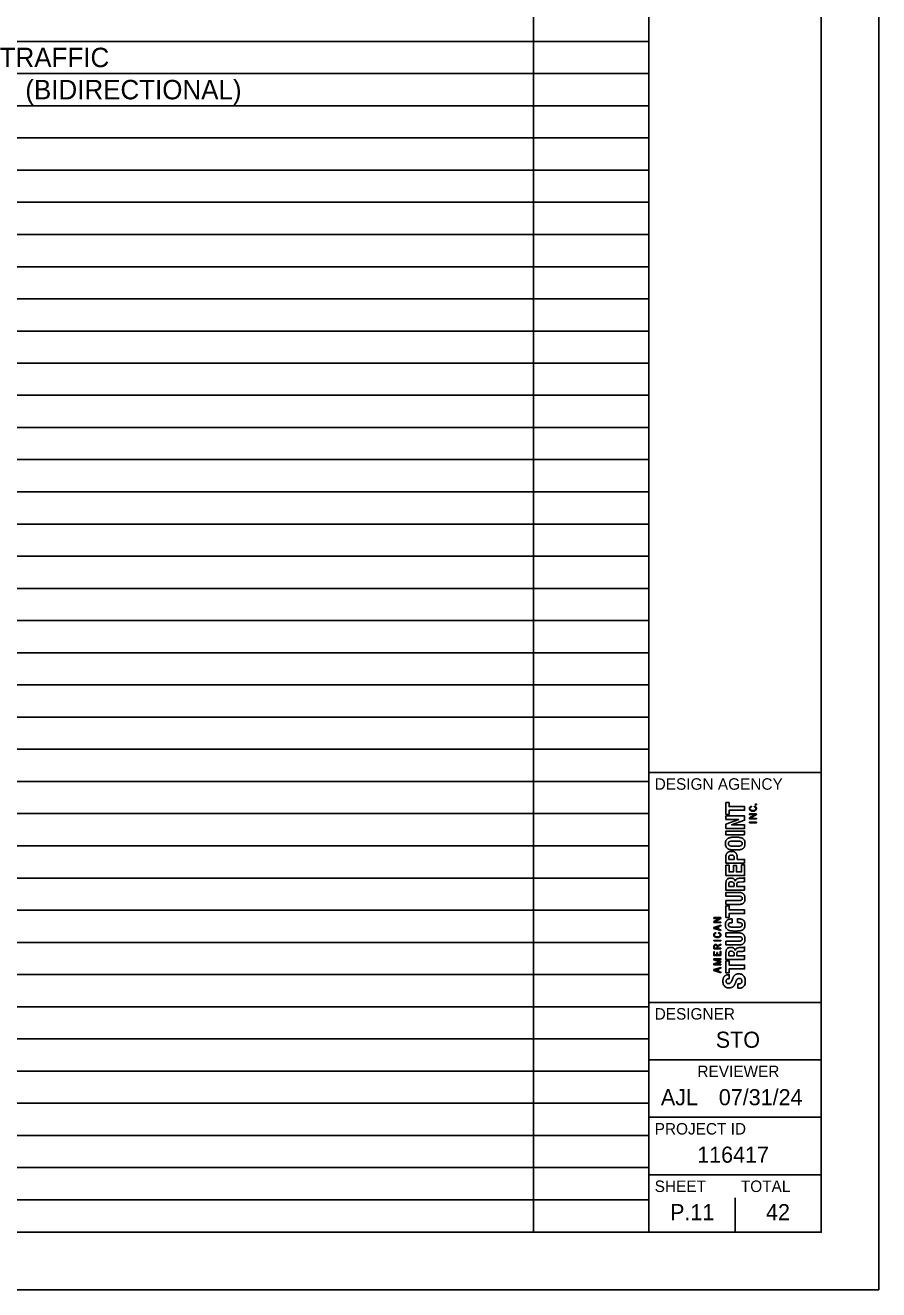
# Model space of a CAD drawing. Extents: x 0 to 34, y 0 to 22.
# Drawn here: x 26.57 to 34, y 0 to 11 of the extents above; entities that cross this region are included whole.
import ezdxf

# ---------------------------------------------------------------- set-up
doc = ezdxf.new("R2010")
doc.units = 0
for name, color, linetype in [('SH_Border', 7, 'Continuous'), ('SH_Cut_Line', 7, 'Continuous'), ('SH_Data', 7, 'Continuous')]:
    doc.layers.add(name, color=color, linetype=linetype)

msp = doc.modelspace()

# ---------------------------------------------------------------- linework, layer by layer
at = {"layer": 'SH_Border'}
for p, q in [((32, 0.5), (32, 21.5)), ((32, 4.5), (33.5, 4.5)), ((32, 2.5), (33.5, 2.5)), ((32, 2), (33.5, 2)), ((32, 1.5), (33.5, 1.5)), ((32, 1), (33.5, 1))]:
    msp.add_line(p, q, dxfattribs=at)
msp.add_lwpolyline([(1.5, 21.5), (33.5, 21.5), (33.5, 0.5), (1.5, 0.5)], close=True, dxfattribs=at)
at = {"layer": 'SH_Cut_Line'}
msp.add_lwpolyline([(0, 0), (34, 0), (34, 22), (0, 22)], close=True, dxfattribs=at)
at = {"layer": 'SH_Data'}
for p, q in [((30.995, 0.502), (30.995, 21.5)), ((32, 0.502), (32, 21.5)), ((1.5, 10.861), (32, 10.861)), ((1.5, 10.581), (32, 10.581)), ((1.5, 10.301), (32, 10.301)), ((1.5, 10.021), (32, 10.021)), ((1.5, 9.741), (32, 9.741)), ((1.5, 9.461), (32, 9.461)), ((1.5, 9.181), (32, 9.181)), ((1.5, 8.901), (32, 8.901)), ((1.5, 8.621), (32, 8.621)), ((1.5, 8.341), (32, 8.341)), ((1.5, 8.062), (32, 8.062)), ((1.5, 7.782), (32, 7.782)), ((1.5, 7.502), (32, 7.502)), ((1.5, 7.222), (32, 7.222)), ((1.5, 6.942), (32, 6.942)), ((1.5, 6.662), (32, 6.662)), ((1.5, 6.382), (32, 6.382)), ((1.5, 6.102), (32, 6.102)), ((1.5, 5.822), (32, 5.822)), ((1.5, 5.542), (32, 5.542)), ((1.5, 5.262), (32, 5.262)), ((1.5, 4.982), (32, 4.982)), ((1.5, 4.702), (32, 4.702)), ((1.5, 4.422), (32, 4.422)), ((1.5, 4.142), (32, 4.142)), ((1.5, 3.862), (32, 3.862)), ((1.5, 3.582), (32, 3.582)), ((32.75, 3.5), (32.75, 3.5)), ((32.75, 3.5), (32.75, 3.5)), ((1.5, 3.302), (32, 3.302)), ((1.5, 3.022), (32, 3.022)), ((1.5, 2.742), (32, 2.742)), ((1.5, 2.462), (32, 2.462)), ((1.5, 2.182), (32, 2.182)), ((1.5, 1.902), (32, 1.902)), ((1.5, 1.622), (32, 1.622)), ((1.5, 1.342), (32, 1.342)), ((1.5, 1.062), (32, 1.062)), ((1.5, 0.782), (32, 0.782)), ((32.75, 0.5), (32.75, 0.8)), ((32.375, 0.675), (32.375, 0.675)), ((1.5, 0.502), (32, 0.502))]:
    msp.add_line(p, q, dxfattribs=at)
for points in [[(32.67, 4.239), (32.697, 4.239), (32.697, 4.204), (32.833, 4.204), (32.833, 4.171), (32.697, 4.171), (32.697, 4.135), (32.67, 4.135), (32.67, 4.239)], [(32.935, 4.218), (32.927, 4.218), (32.927, 4.225), (32.935, 4.225), (32.935, 4.218)], [(32.67, 4.051), (32.781, 4.091), (32.781, 4.092), (32.67, 4.092), (32.67, 4.122), (32.833, 4.122), (32.833, 4.084), (32.719, 4.044), (32.719, 4.044), (32.833, 4.044), (32.833, 4.013), (32.67, 4.013), (32.67, 4.051)], [(32.875, 4.096), (32.875, 4.105), (32.925, 4.134), (32.925, 4.134), (32.875, 4.134), (32.875, 4.139), (32.935, 4.139), (32.935, 4.134), (32.88, 4.102), (32.88, 4.101), (32.935, 4.101), (32.935, 4.096), (32.875, 4.096)], [(32.833, 3.957), (32.67, 3.957), (32.67, 3.99), (32.833, 3.99), (32.833, 3.957)], [(32.875, 4.061), (32.875, 4.067), (32.935, 4.067), (32.935, 4.061), (32.875, 4.061)], [(32.833, 3.712), (32.67, 3.712), (32.67, 3.769)], [(32.694, 3.744), (32.743, 3.744), (32.743, 3.759)], [(32.694, 3.758), (32.694, 3.744)], [(32.768, 3.762), (32.768, 3.744), (32.833, 3.744), (32.833, 3.712)], [(32.67, 3.694), (32.697, 3.694), (32.697, 3.635), (32.735, 3.635), (32.735, 3.69), (32.762, 3.69), (32.762, 3.635), (32.806, 3.635), (32.806, 3.696), (32.833, 3.696), (32.833, 3.603), (32.67, 3.603), (32.67, 3.694)], [(32.833, 3.476), (32.67, 3.476), (32.67, 3.537)], [(32.694, 3.525), (32.694, 3.509)], [(32.694, 3.509), (32.741, 3.509), (32.741, 3.523)], [(32.752, 3.554), (32.752, 3.554)], [(32.764, 3.527), (32.764, 3.509), (32.833, 3.509), (32.833, 3.476)], [(32.816, 3.548), (32.784, 3.547)], [(32.832, 3.587), (32.833, 3.587), (32.833, 3.552)], [(32.67, 3.341), (32.697, 3.341), (32.697, 3.305), (32.833, 3.305), (32.833, 3.273), (32.697, 3.273), (32.697, 3.237), (32.67, 3.237), (32.67, 3.341)], [(32.565, 3.194), (32.565, 3.203), (32.615, 3.231), (32.615, 3.231), (32.565, 3.231), (32.565, 3.237), (32.625, 3.237), (32.625, 3.231), (32.569, 3.199), (32.569, 3.199), (32.625, 3.199), (32.625, 3.194), (32.565, 3.194)], [(32.625, 3.125), (32.565, 3.144), (32.565, 3.152), (32.625, 3.171), (32.625, 3.165), (32.605, 3.159), (32.605, 3.137), (32.625, 3.131), (32.625, 3.125)], [(32.601, 3.138), (32.601, 3.158), (32.569, 3.148), (32.569, 3.148), (32.601, 3.138)], [(32.565, 3.034), (32.565, 3.039), (32.625, 3.039), (32.625, 3.034), (32.565, 3.034)], [(32.596, 2.992), (32.625, 3.006), (32.625, 3), (32.597, 2.987), (32.597, 2.971), (32.625, 2.971), (32.625, 2.966), (32.565, 2.966), (32.565, 2.986)], [(32.569, 2.971), (32.593, 2.971), (32.593, 2.986)], [(32.569, 2.986), (32.569, 2.971)], [(32.832, 2.984), (32.833, 2.984), (32.833, 2.949)], [(32.625, 2.907), (32.565, 2.907), (32.565, 2.941), (32.569, 2.941), (32.569, 2.913), (32.591, 2.913), (32.591, 2.933), (32.596, 2.933), (32.596, 2.913), (32.62, 2.913), (32.62, 2.943), (32.625, 2.943), (32.625, 2.907)], [(32.625, 2.826), (32.565, 2.826), (32.565, 2.836), (32.615, 2.852), (32.615, 2.853), (32.565, 2.869), (32.565, 2.879), (32.625, 2.879), (32.625, 2.873), (32.569, 2.873), (32.569, 2.873), (32.625, 2.855), (32.625, 2.85), (32.569, 2.832), (32.569, 2.832), (32.625, 2.832), (32.625, 2.826)], [(32.833, 2.873), (32.67, 2.873), (32.67, 2.934)], [(32.694, 2.922), (32.694, 2.906)], [(32.694, 2.906), (32.741, 2.906), (32.741, 2.92)], [(32.752, 2.951), (32.752, 2.951)], [(32.764, 2.924), (32.764, 2.906), (32.833, 2.906), (32.833, 2.873)], [(32.816, 2.944), (32.784, 2.944)], [(32.625, 2.758), (32.565, 2.777), (32.565, 2.785), (32.625, 2.804), (32.625, 2.798), (32.605, 2.792), (32.605, 2.769), (32.625, 2.763), (32.625, 2.758)], [(32.601, 2.771), (32.601, 2.791), (32.569, 2.781), (32.569, 2.781), (32.601, 2.771)], [(32.67, 2.86), (32.697, 2.86), (32.697, 2.824), (32.833, 2.824), (32.833, 2.791), (32.697, 2.791), (32.697, 2.756), (32.67, 2.756), (32.67, 2.86)]]:
    msp.add_lwpolyline(points, dxfattribs=at)
for points in [[(32.893, 4.201), (32.889, 4.199), (32.885, 4.197), (32.883, 4.195), (32.88, 4.193), (32.879, 4.19), (32.879, 4.186), (32.879, 4.183), (32.88, 4.181), (32.881, 4.178), (32.882, 4.176), (32.884, 4.175), (32.887, 4.173), (32.889, 4.172), (32.892, 4.171), (32.895, 4.17), (32.898, 4.169), (32.902, 4.169), (32.905, 4.169), (32.909, 4.169), (32.912, 4.169), (32.915, 4.17), (32.919, 4.171), (32.921, 4.172), (32.924, 4.173), (32.926, 4.175), (32.928, 4.176), (32.929, 4.179), (32.931, 4.181), (32.931, 4.184), (32.931, 4.187), (32.931, 4.189), (32.931, 4.191), (32.93, 4.193), (32.929, 4.194), (32.928, 4.196), (32.927, 4.197), (32.926, 4.198), (32.924, 4.199), (32.922, 4.2), (32.921, 4.2), (32.919, 4.201), (32.917, 4.202), (32.917, 4.202), (32.918, 4.207), (32.918, 4.207), (32.92, 4.206), (32.923, 4.205), (32.925, 4.204), (32.927, 4.203), (32.929, 4.202), (32.931, 4.2), (32.932, 4.199), (32.934, 4.197), (32.934, 4.195), (32.935, 4.192), (32.936, 4.19), (32.936, 4.187), (32.936, 4.183), (32.935, 4.18), (32.934, 4.177), (32.932, 4.174), (32.93, 4.172), (32.927, 4.17), (32.925, 4.168), (32.921, 4.166), (32.918, 4.165), (32.914, 4.164), (32.91, 4.164), (32.905, 4.164), (32.901, 4.164), (32.896, 4.164), (32.893, 4.165), (32.889, 4.166), (32.886, 4.168), (32.883, 4.17), (32.88, 4.172), (32.878, 4.174), (32.877, 4.177), (32.875, 4.18), (32.875, 4.183), (32.875, 4.187), (32.875, 4.189), (32.875, 4.192), (32.876, 4.194), (32.877, 4.196), (32.878, 4.198), (32.88, 4.199), (32.881, 4.201), (32.883, 4.202), (32.885, 4.203), (32.887, 4.204), (32.889, 4.205), (32.892, 4.206), (32.892, 4.206), (32.893, 4.201), (32.893, 4.201)], [(32.751, 3.826), (32.739, 3.826), (32.727, 3.826), (32.717, 3.828), (32.706, 3.829), (32.697, 3.831), (32.69, 3.835), (32.682, 3.839), (32.677, 3.845), (32.672, 3.852), (32.668, 3.859), (32.666, 3.869), (32.666, 3.882), (32.666, 3.894), (32.668, 3.904), (32.672, 3.911), (32.677, 3.918), (32.682, 3.924), (32.69, 3.928), (32.697, 3.932), (32.706, 3.934), (32.717, 3.936), (32.727, 3.937), (32.739, 3.937), (32.751, 3.937), (32.758, 3.937), (32.764, 3.937), (32.771, 3.937)], [(32.751, 3.859), (32.762, 3.859), (32.771, 3.859), (32.779, 3.859), (32.787, 3.86), (32.793, 3.861), (32.798, 3.863), (32.803, 3.864), (32.806, 3.867), (32.808, 3.87), (32.81, 3.873), (32.812, 3.877), (32.812, 3.882), (32.812, 3.886), (32.81, 3.89), (32.808, 3.893), (32.806, 3.896), (32.803, 3.899), (32.798, 3.9), (32.793, 3.902), (32.787, 3.903), (32.779, 3.904), (32.771, 3.904), (32.762, 3.904), (32.751, 3.904), (32.74, 3.904), (32.731, 3.904), (32.723, 3.904), (32.716, 3.903), (32.709, 3.902), (32.704, 3.9), (32.7, 3.899), (32.696, 3.896), (32.694, 3.893), (32.692, 3.89), (32.691, 3.886), (32.691, 3.882), (32.691, 3.877), (32.692, 3.873), (32.694, 3.87), (32.696, 3.867), (32.7, 3.864), (32.704, 3.863), (32.709, 3.861), (32.716, 3.86), (32.723, 3.859), (32.731, 3.859), (32.74, 3.859), (32.751, 3.859)], [(32.771, 3.937), (32.776, 3.936), (32.781, 3.936), (32.785, 3.936), (32.796, 3.934), (32.805, 3.932), (32.812, 3.928), (32.82, 3.924), (32.825, 3.918), (32.83, 3.911), (32.834, 3.904), (32.836, 3.894), (32.836, 3.882), (32.836, 3.869), (32.834, 3.859), (32.83, 3.852), (32.825, 3.845), (32.82, 3.839), (32.812, 3.835), (32.805, 3.831), (32.796, 3.829), (32.785, 3.828), (32.775, 3.826), (32.763, 3.826), (32.751, 3.826)], [(32.67, 3.769), (32.67, 3.777), (32.671, 3.784), (32.674, 3.79), (32.677, 3.796), (32.68, 3.8), (32.685, 3.804), (32.689, 3.807), (32.695, 3.81), (32.701, 3.812), (32.706, 3.813), (32.712, 3.814), (32.719, 3.814), (32.727, 3.814), (32.734, 3.813), (32.741, 3.81), (32.747, 3.808), (32.752, 3.804), (32.756, 3.8), (32.76, 3.795), (32.763, 3.79), (32.765, 3.783), (32.767, 3.777), (32.768, 3.77), (32.768, 3.762)], [(32.743, 3.759), (32.743, 3.766), (32.741, 3.771), (32.737, 3.775), (32.733, 3.779), (32.727, 3.781), (32.719, 3.781), (32.711, 3.781), (32.705, 3.779), (32.7, 3.776), (32.696, 3.772), (32.694, 3.766), (32.694, 3.758)], [(32.67, 3.537), (32.67, 3.551), (32.673, 3.562), (32.68, 3.569), (32.687, 3.577), (32.698, 3.581), (32.712, 3.581), (32.723, 3.581), (32.732, 3.579), (32.739, 3.574), (32.745, 3.57), (32.75, 3.563), (32.752, 3.554)], [(32.741, 3.523), (32.741, 3.531), (32.739, 3.537), (32.735, 3.542), (32.732, 3.546), (32.725, 3.548), (32.717, 3.548), (32.702, 3.548), (32.694, 3.54), (32.694, 3.525)], [(32.752, 3.554), (32.753, 3.559), (32.755, 3.564), (32.757, 3.567), (32.759, 3.571), (32.762, 3.573), (32.766, 3.575), (32.769, 3.577), (32.774, 3.578), (32.78, 3.579), (32.786, 3.58), (32.794, 3.58), (32.802, 3.58), (32.811, 3.58), (32.818, 3.581), (32.822, 3.582), (32.827, 3.582), (32.83, 3.584), (32.832, 3.587)], [(32.784, 3.547), (32.778, 3.546), (32.773, 3.545), (32.769, 3.542), (32.766, 3.539), (32.764, 3.534), (32.764, 3.527)], [(32.833, 3.552), (32.831, 3.55), (32.828, 3.549), (32.825, 3.549), (32.822, 3.548), (32.819, 3.548), (32.816, 3.548)], [(32.67, 3.385), (32.67, 3.385), (32.783, 3.385), (32.783, 3.385), (32.787, 3.385), (32.791, 3.385), (32.795, 3.386), (32.798, 3.387), (32.801, 3.388), (32.803, 3.389), (32.806, 3.39), (32.808, 3.392), (32.809, 3.395), (32.811, 3.397), (32.812, 3.401), (32.812, 3.404), (32.812, 3.408), (32.811, 3.411), (32.809, 3.414), (32.808, 3.417), (32.806, 3.418), (32.803, 3.42), (32.801, 3.421), (32.798, 3.422), (32.795, 3.423), (32.791, 3.423), (32.787, 3.424), (32.783, 3.424), (32.783, 3.424), (32.67, 3.424), (32.67, 3.424), (32.67, 3.424), (32.67, 3.457), (32.67, 3.457), (32.67, 3.457), (32.783, 3.457), (32.783, 3.457), (32.794, 3.457), (32.802, 3.455), (32.809, 3.452), (32.816, 3.449), (32.821, 3.445), (32.825, 3.441), (32.829, 3.436), (32.832, 3.43), (32.834, 3.424), (32.835, 3.418), (32.836, 3.411), (32.836, 3.404), (32.836, 3.398), (32.835, 3.391), (32.834, 3.385), (32.833, 3.379), (32.83, 3.373), (32.826, 3.368), (32.822, 3.363), (32.817, 3.36), (32.81, 3.357), (32.803, 3.354), (32.794, 3.352), (32.783, 3.352), (32.783, 3.352), (32.67, 3.352), (32.67, 3.352), (32.67, 3.352), (32.67, 3.385), (32.67, 3.385)], [(32.725, 3.193), (32.713, 3.193), (32.704, 3.192), (32.699, 3.189), (32.693, 3.186), (32.691, 3.181), (32.691, 3.174), (32.691, 3.17), (32.692, 3.166), (32.694, 3.163), (32.696, 3.161), (32.7, 3.159), (32.705, 3.157), (32.71, 3.156), (32.716, 3.155), (32.724, 3.154), (32.732, 3.153), (32.742, 3.153), (32.753, 3.153), (32.766, 3.153), (32.776, 3.153), (32.783, 3.154), (32.791, 3.155), (32.797, 3.156), (32.801, 3.158), (32.805, 3.16), (32.808, 3.162), (32.809, 3.165), (32.811, 3.168), (32.812, 3.171), (32.812, 3.174), (32.812, 3.177), (32.811, 3.18), (32.81, 3.182), (32.809, 3.185), (32.807, 3.187), (32.804, 3.189), (32.801, 3.191), (32.797, 3.192), (32.792, 3.193), (32.786, 3.194), (32.779, 3.195), (32.77, 3.195), (32.77, 3.195), (32.77, 3.228), (32.77, 3.228), (32.779, 3.228), (32.787, 3.227), (32.795, 3.226), (32.803, 3.224), (32.81, 3.222), (32.816, 3.218), (32.822, 3.214), (32.827, 3.209), (32.831, 3.202), (32.834, 3.196), (32.836, 3.187), (32.836, 3.176), (32.836, 3.163), (32.834, 3.154), (32.83, 3.146), (32.825, 3.139), (32.82, 3.133), (32.812, 3.129), (32.805, 3.126), (32.796, 3.123), (32.785, 3.122), (32.775, 3.121), (32.763, 3.12), (32.751, 3.12), (32.739, 3.12), (32.727, 3.121), (32.717, 3.122), (32.706, 3.123), (32.697, 3.126), (32.69, 3.129), (32.682, 3.133), (32.677, 3.139), (32.672, 3.146), (32.668, 3.154), (32.666, 3.163), (32.666, 3.176), (32.666, 3.188), (32.668, 3.197), (32.672, 3.204), (32.676, 3.21), (32.681, 3.215), (32.687, 3.219), (32.692, 3.222), (32.699, 3.224), (32.706, 3.225), (32.712, 3.226), (32.719, 3.226), (32.725, 3.226), (32.725, 3.226), (32.725, 3.193), (32.725, 3.193)], [(32.582, 3.101), (32.578, 3.1), (32.575, 3.098), (32.572, 3.095), (32.57, 3.093), (32.569, 3.09), (32.569, 3.086), (32.569, 3.083), (32.569, 3.081), (32.571, 3.079), (32.572, 3.077), (32.574, 3.075), (32.576, 3.074), (32.579, 3.072), (32.581, 3.071), (32.585, 3.07), (32.588, 3.07), (32.591, 3.069), (32.595, 3.069), (32.598, 3.069), (32.602, 3.07), (32.605, 3.07), (32.608, 3.071), (32.611, 3.072), (32.613, 3.074), (32.616, 3.075), (32.618, 3.077), (32.619, 3.079), (32.62, 3.081), (32.621, 3.084), (32.621, 3.087), (32.621, 3.089), (32.62, 3.091), (32.62, 3.093), (32.619, 3.095), (32.618, 3.096), (32.617, 3.097), (32.615, 3.098), (32.614, 3.099), (32.612, 3.1), (32.61, 3.101), (32.608, 3.102), (32.606, 3.102), (32.606, 3.102), (32.607, 3.107), (32.607, 3.107), (32.61, 3.107), (32.612, 3.106), (32.615, 3.105), (32.617, 3.104), (32.619, 3.102), (32.62, 3.101), (32.622, 3.099), (32.623, 3.097), (32.624, 3.095), (32.625, 3.093), (32.625, 3.09), (32.625, 3.087), (32.625, 3.083), (32.625, 3.08), (32.623, 3.077), (32.622, 3.074), (32.62, 3.072), (32.617, 3.07), (32.614, 3.068), (32.611, 3.067), (32.607, 3.066), (32.604, 3.065), (32.599, 3.064), (32.595, 3.064), (32.59, 3.064), (32.586, 3.065), (32.582, 3.066), (32.579, 3.067), (32.575, 3.068), (32.573, 3.07), (32.57, 3.072), (32.568, 3.074), (32.566, 3.077), (32.565, 3.08), (32.564, 3.083), (32.564, 3.087), (32.564, 3.09), (32.565, 3.092), (32.566, 3.094), (32.566, 3.096), (32.568, 3.098), (32.569, 3.099), (32.571, 3.101), (32.572, 3.102), (32.575, 3.103), (32.577, 3.104), (32.579, 3.105), (32.581, 3.106), (32.581, 3.106), (32.582, 3.101), (32.582, 3.101)], [(32.67, 3.032), (32.67, 3.032), (32.783, 3.032), (32.783, 3.032), (32.787, 3.032), (32.791, 3.033), (32.795, 3.033), (32.798, 3.034), (32.801, 3.035), (32.803, 3.036), (32.806, 3.038), (32.808, 3.04), (32.809, 3.042), (32.811, 3.045), (32.812, 3.048), (32.812, 3.052), (32.812, 3.056), (32.811, 3.059), (32.809, 3.061), (32.808, 3.064), (32.806, 3.066), (32.803, 3.067), (32.801, 3.069), (32.798, 3.07), (32.795, 3.07), (32.791, 3.071), (32.787, 3.071), (32.783, 3.071), (32.783, 3.071), (32.67, 3.071), (32.67, 3.071), (32.67, 3.071), (32.67, 3.104), (32.67, 3.104), (32.67, 3.104), (32.783, 3.104), (32.783, 3.104), (32.794, 3.104), (32.802, 3.102), (32.809, 3.1), (32.816, 3.097), (32.821, 3.093), (32.825, 3.088), (32.829, 3.083), (32.832, 3.077), (32.834, 3.071), (32.835, 3.065), (32.836, 3.058), (32.836, 3.052), (32.836, 3.045), (32.835, 3.039), (32.834, 3.032), (32.833, 3.026), (32.83, 3.021), (32.826, 3.016), (32.822, 3.011), (32.817, 3.007), (32.81, 3.004), (32.803, 3.001), (32.794, 3), (32.783, 3), (32.783, 3), (32.67, 3), (32.67, 3), (32.67, 3), (32.67, 3.032), (32.67, 3.032)], [(32.565, 2.986), (32.565, 2.992), (32.566, 2.996), (32.569, 2.999), (32.572, 3.003), (32.576, 3.004), (32.581, 3.004), (32.585, 3.004), (32.588, 3.003), (32.591, 3.001), (32.593, 2.999), (32.595, 2.996), (32.596, 2.992)], [(32.593, 2.986), (32.593, 2.99), (32.592, 2.993), (32.59, 2.995), (32.588, 2.997), (32.585, 2.999), (32.581, 2.999), (32.577, 2.999), (32.575, 2.998), (32.573, 2.995), (32.57, 2.993), (32.569, 2.99), (32.569, 2.986)], [(32.67, 2.934), (32.67, 2.948), (32.673, 2.958), (32.68, 2.966), (32.687, 2.974), (32.698, 2.978), (32.712, 2.978), (32.723, 2.978), (32.732, 2.975), (32.739, 2.971), (32.745, 2.967), (32.75, 2.96), (32.752, 2.951)], [(32.752, 2.951), (32.753, 2.956), (32.755, 2.961), (32.757, 2.964), (32.759, 2.967), (32.762, 2.97), (32.766, 2.972), (32.769, 2.974), (32.774, 2.975), (32.78, 2.976), (32.786, 2.976), (32.794, 2.977), (32.802, 2.977), (32.811, 2.977), (32.818, 2.978), (32.822, 2.978), (32.827, 2.979), (32.83, 2.981), (32.832, 2.984)], [(32.741, 2.92), (32.741, 2.928), (32.739, 2.934), (32.735, 2.938), (32.732, 2.943), (32.725, 2.945), (32.717, 2.945), (32.702, 2.945), (32.694, 2.937), (32.694, 2.922)], [(32.784, 2.944), (32.778, 2.943), (32.773, 2.942), (32.769, 2.939), (32.766, 2.936), (32.764, 2.931), (32.764, 2.924)], [(32.833, 2.949), (32.831, 2.947), (32.828, 2.946), (32.825, 2.945), (32.822, 2.945), (32.819, 2.945), (32.816, 2.944)], [(32.775, 2.661), (32.775, 2.661), (32.781, 2.661), (32.781, 2.661), (32.785, 2.661), (32.789, 2.662), (32.793, 2.662), (32.796, 2.663), (32.799, 2.664), (32.801, 2.666), (32.804, 2.668), (32.806, 2.671), (32.807, 2.674), (32.809, 2.677), (32.809, 2.681), (32.809, 2.686), (32.809, 2.692), (32.807, 2.697), (32.804, 2.701), (32.8, 2.706), (32.794, 2.708), (32.786, 2.708), (32.782, 2.708), (32.779, 2.708), (32.776, 2.707), (32.773, 2.705), (32.77, 2.704), (32.767, 2.701), (32.765, 2.698), (32.763, 2.695), (32.761, 2.691), (32.759, 2.687), (32.757, 2.681), (32.755, 2.675), (32.752, 2.667), (32.749, 2.66), (32.745, 2.654), (32.742, 2.647), (32.738, 2.642), (32.734, 2.638), (32.73, 2.634), (32.725, 2.631), (32.719, 2.629), (32.713, 2.628), (32.706, 2.627), (32.699, 2.627), (32.68, 2.627), (32.667, 2.632), (32.658, 2.642), (32.649, 2.652), (32.644, 2.666), (32.644, 2.684), (32.644, 2.692), (32.645, 2.7), (32.647, 2.707), (32.649, 2.714), (32.651, 2.72), (32.656, 2.725), (32.66, 2.73), (32.665, 2.734), (32.671, 2.737), (32.677, 2.74), (32.685, 2.741), (32.694, 2.741), (32.694, 2.741), (32.699, 2.741), (32.699, 2.741), (32.699, 2.741), (32.699, 2.705), (32.699, 2.705), (32.69, 2.705), (32.683, 2.704), (32.679, 2.701), (32.674, 2.697), (32.671, 2.692), (32.671, 2.685), (32.671, 2.681), (32.672, 2.678), (32.673, 2.675), (32.675, 2.672), (32.676, 2.67), (32.678, 2.668), (32.68, 2.667), (32.682, 2.665), (32.685, 2.665), (32.688, 2.664), (32.69, 2.664), (32.693, 2.664), (32.699, 2.664), (32.704, 2.665), (32.707, 2.668), (32.711, 2.67), (32.715, 2.675), (32.718, 2.683), (32.718, 2.683), (32.731, 2.712), (32.731, 2.712), (32.734, 2.719), (32.737, 2.725), (32.74, 2.729), (32.744, 2.734), (32.747, 2.737), (32.751, 2.74), (32.755, 2.743), (32.76, 2.745), (32.764, 2.746), (32.769, 2.747), (32.774, 2.747), (32.78, 2.747), (32.799, 2.747), (32.814, 2.742), (32.823, 2.73), (32.832, 2.719), (32.837, 2.703), (32.837, 2.683), (32.837, 2.662), (32.832, 2.647), (32.823, 2.638), (32.813, 2.628), (32.8, 2.624), (32.783, 2.624), (32.783, 2.624), (32.775, 2.624), (32.775, 2.624), (32.775, 2.624), (32.775, 2.661), (32.775, 2.661)]]:
    msp.add_open_spline(points, degree=3, dxfattribs=at)

# ---------------------------------------------------------------- texts
for s, height, p in [(' TRAFFIC', 0.1689, (26.286, 10.637)), (' (BIDIRECTIONAL)', 0.16891, (26.509, 10.357)), ('DESIGN AGENCY', 0.1, (32.05, 4.35)), ('DESIGNER', 0.1, (32.05, 2.35)), ('STO', 0.14, (32.582, 2.105)), ('REVIEWER', 0.1, (32.422, 1.85)), ('AJL', 0.14, (32.104, 1.605)), ('07/31/24', 0.14, (32.608, 1.605)), ('PROJECT ID', 0.1, (32.05, 1.35)), ('116417', 0.14, (32.42, 1.105)), ('SHEET', 0.1, (32.05, 0.85)), ('TOTAL', 0.1, (32.8, 0.85)), ('P.11', 0.14, (32.184, 0.605)), ('42', 0.14, (33.019, 0.605))]:
    msp.add_text(s, height=height, dxfattribs=at).set_placement(p)

doc.saveas('drawing.dxf')
